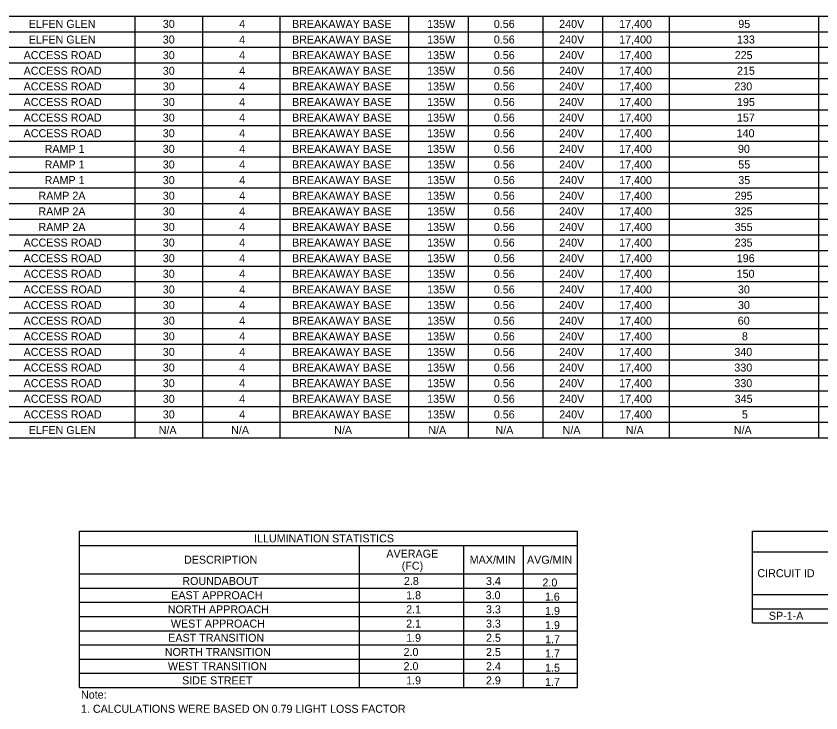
# Model space of a CAD drawing. Extents: x 0.17 to 2.79, y 0.05 to 1.72.
# Drawn here: x 0.862 to 1.859, y 0.093 to 0.956 of the extents above; entities that cross this region are included whole.
import ezdxf

# ---------------------------------------------------------------- set-up
doc = ezdxf.new("R2010")
doc.units = 0
doc.layers.add('Default', color=7, linetype='Continuous')
doc.layers.add('No_Plot', color=7, linetype='Continuous')

msp = doc.modelspace()

# ---------------------------------------------------------------- linework, layer by layer
at = {"layer": 'Default'}
for p, q in [((0.32609, 0.95626), (2.52066, 0.95626)), ((1.0098, 0.43358), (1.0098, 0.95626)), ((1.0934, 0.43358), (1.0934, 0.95626)), ((1.18931, 0.43358), (1.18931, 0.95626)), ((1.34858, 0.43358), (1.34858, 0.95626)), ((1.42249, 0.43358), (1.42249, 0.95626)), ((1.51489, 0.43358), (1.51489, 0.95626)), ((1.5888, 0.43358), (1.5888, 0.95626)), ((1.67152, 0.43358), (1.67152, 0.95626)), ((1.8563, 0.43358), (1.8563, 0.95626)), ((0.32609, 0.9369), (2.52066, 0.9369)), ((0.32609, 0.91754), (2.52066, 0.91754)), ((0.32609, 0.89819), (2.52066, 0.89819)), ((0.32609, 0.87883), (2.52066, 0.87883)), ((0.32609, 0.85947), (2.52066, 0.85947)), ((0.32609, 0.84011), (2.52066, 0.84011)), ((0.32609, 0.82075), (2.52066, 0.82075)), ((0.32609, 0.80139), (2.52066, 0.80139)), ((0.32609, 0.78203), (2.52066, 0.78203)), ((0.32609, 0.76268), (2.52066, 0.76268)), ((0.32609, 0.74332), (2.52066, 0.74332)), ((0.32609, 0.72396), (2.52066, 0.72396)), ((0.32609, 0.7046), (2.52066, 0.7046)), ((0.32609, 0.68524), (2.52066, 0.68524)), ((0.32609, 0.66588), (2.52066, 0.66588)), ((0.32609, 0.64652), (2.52066, 0.64652)), ((0.32609, 0.62716), (2.52066, 0.62716)), ((0.32609, 0.60781), (2.52066, 0.60781)), ((0.32609, 0.58845), (2.52066, 0.58845)), ((0.32609, 0.56909), (2.52066, 0.56909)), ((0.32609, 0.54973), (2.52066, 0.54973)), ((0.32609, 0.53037), (2.52066, 0.53037)), ((0.32609, 0.51101), (2.52066, 0.51101)), ((0.32609, 0.49165), (2.52066, 0.49165)), ((0.32609, 0.4723), (2.52066, 0.4723)), ((0.32609, 0.45294), (2.52066, 0.45294)), ((0.32609, 0.43358), (2.52066, 0.43358)), ((0.94083, 0.31777), (1.55767, 0.31777)), ((0.94083, 0.12418), (0.94083, 0.31777)), ((1.55767, 0.12418), (1.55767, 0.31777)), ((1.7742, 0.31777), (2.64886, 0.31777)), ((1.7742, 0.20426), (1.7742, 0.31777)), ((0.94083, 0.30017), (1.55767, 0.30017)), ((1.28753, 0.12418), (1.28753, 0.30017)), ((1.41688, 0.12418), (1.41688, 0.30017)), ((1.49079, 0.12418), (1.49079, 0.30017)), ((1.7742, 0.29225), (2.64886, 0.29225)), ((0.94083, 0.26497), (1.55767, 0.26497)), ((0.94083, 0.24737), (1.55767, 0.24737)), ((1.7742, 0.23946), (2.64886, 0.23946)), ((0.94083, 0.22978), (1.55767, 0.22978)), ((1.7742, 0.22186), (2.64886, 0.22186)), ((0.94083, 0.21218), (1.55767, 0.21218)), ((1.7742, 0.20426), (2.64886, 0.20426)), ((0.94083, 0.19458), (1.55767, 0.19458)), ((0.94083, 0.17698), (1.55767, 0.17698)), ((0.94083, 0.15938), (1.55767, 0.15938)), ((0.94083, 0.14178), (1.55767, 0.14178)), ((0.94083, 0.12418), (1.55767, 0.12418))]:
    msp.add_line(p, q, dxfattribs=at)
at = {"layer": 'No_Plot'}
for p, q in [((0.94083, 0.31777), (0.94083, 0.31777)), ((1.7742, 0.31777), (1.7742, 0.31777))]:
    msp.add_line(p, q, dxfattribs=at)

# ---------------------------------------------------------------- texts
at = {"layer": 'Default'}
for s, height, p in [('ELFEN GLEN', 0.009927, (0.87792, 0.94162)), ('30', 0.009927, (1.0439, 0.94162)), ('4', 0.00993, (1.13854, 0.94162)), ('BREAKAWAY BASE', 0.0099275, (1.20399, 0.94162)), ('135W', 0.009927, (1.37131, 0.94162)), ('0.56', 0.009927, (1.45388, 0.94162)), ('240V', 0.009927, (1.53484, 0.94162)), ('17,400', 0.009927, (1.60909, 0.94162)), ('95', 0.009927, (1.75664, 0.94162)), ('ELFEN GLEN', 0.009927, (0.87792, 0.92226)), ('30', 0.009927, (1.0439, 0.92226)), ('4', 0.00993, (1.13854, 0.92226)), ('BREAKAWAY BASE', 0.0099275, (1.20399, 0.92226)), ('135W', 0.009927, (1.37131, 0.92226)), ('0.56', 0.009927, (1.45388, 0.92226)), ('240V', 0.009927, (1.53484, 0.92226)), ('17,400', 0.009927, (1.60909, 0.92226)), ('133', 0.009927, (1.755, 0.92226)), ('ACCESS ROAD', 0.0099275, (0.87159, 0.9029)), ('30', 0.009927, (1.0439, 0.9029)), ('4', 0.00993, (1.13854, 0.9029)), ('BREAKAWAY BASE', 0.0099275, (1.20399, 0.9029)), ('135W', 0.009927, (1.37131, 0.9029)), ('0.56', 0.009927, (1.45388, 0.9029)), ('240V', 0.009927, (1.53484, 0.9029)), ('17,400', 0.009927, (1.60909, 0.9029)), ('225', 0.009927, (1.75219, 0.9029)), ('ACCESS ROAD', 0.0099275, (0.87159, 0.88354)), ('30', 0.009927, (1.0439, 0.88354)), ('4', 0.00993, (1.13854, 0.88354)), ('BREAKAWAY BASE', 0.0099275, (1.20399, 0.88354)), ('135W', 0.009927, (1.37131, 0.88354)), ('0.56', 0.009927, (1.45388, 0.88354)), ('240V', 0.009927, (1.53484, 0.88354)), ('17,400', 0.009927, (1.60909, 0.88354)), ('215', 0.009927, (1.755, 0.88354)), ('ACCESS ROAD', 0.0099275, (0.87159, 0.86418)), ('30', 0.009927, (1.0439, 0.86418)), ('4', 0.00993, (1.13854, 0.86418)), ('BREAKAWAY BASE', 0.0099275, (1.20399, 0.86418)), ('135W', 0.009927, (1.37131, 0.86418)), ('0.56', 0.009927, (1.45388, 0.86418)), ('240V', 0.009927, (1.53484, 0.86418)), ('17,400', 0.009927, (1.60909, 0.86418)), ('230', 0.009927, (1.75176, 0.86418)), ('ACCESS ROAD', 0.0099275, (0.87159, 0.84483)), ('30', 0.009927, (1.0439, 0.84483)), ('4', 0.00993, (1.13854, 0.84483)), ('BREAKAWAY BASE', 0.0099275, (1.20399, 0.84483)), ('135W', 0.009927, (1.37131, 0.84483)), ('0.56', 0.009927, (1.45388, 0.84483)), ('240V', 0.009927, (1.53484, 0.84483)), ('17,400', 0.009927, (1.60909, 0.84483)), ('195', 0.009927, (1.755, 0.84483)), ('ACCESS ROAD', 0.0099275, (0.87159, 0.82547)), ('30', 0.009927, (1.0439, 0.82547)), ('4', 0.00993, (1.13854, 0.82547)), ('BREAKAWAY BASE', 0.0099275, (1.20399, 0.82547)), ('135W', 0.009927, (1.37131, 0.82547)), ('0.56', 0.009927, (1.45388, 0.82547)), ('240V', 0.009927, (1.53484, 0.82547)), ('17,400', 0.009927, (1.60909, 0.82547)), ('157', 0.009927, (1.755, 0.82547)), ('ACCESS ROAD', 0.0099275, (0.87159, 0.80611)), ('30', 0.009927, (1.0439, 0.80611)), ('4', 0.00993, (1.13854, 0.80611)), ('BREAKAWAY BASE', 0.0099275, (1.20399, 0.80611)), ('135W', 0.009927, (1.37131, 0.80611)), ('0.56', 0.009927, (1.45388, 0.80611)), ('240V', 0.009927, (1.53484, 0.80611)), ('17,400', 0.009927, (1.60909, 0.80611)), ('140', 0.009927, (1.75457, 0.80611)), ('RAMP 1', 0.009927, (0.89758, 0.78675)), ('30', 0.009927, (1.0439, 0.78675)), ('4', 0.00993, (1.13854, 0.78675)), ('BREAKAWAY BASE', 0.0099275, (1.20399, 0.78675)), ('135W', 0.009927, (1.37131, 0.78675)), ('0.56', 0.009927, (1.45388, 0.78675)), ('240V', 0.009927, (1.53484, 0.78675)), ('17,400', 0.009927, (1.60909, 0.78675)), ('90', 0.009927, (1.75621, 0.78675)), ('30', 0.009927, (1.0439, 0.76739)), ('BREAKAWAY BASE', 0.0099275, (1.20399, 0.76739)), ('135W', 0.009927, (1.37131, 0.76739)), ('0.56', 0.009927, (1.45388, 0.76739)), ('240V', 0.009927, (1.53484, 0.76739)), ('17,400', 0.009927, (1.60909, 0.76739)), ('RAMP 1', 0.009927, (0.89758, 0.76739)), ('4', 0.00993, (1.13854, 0.76739)), ('55', 0.009927, (1.75664, 0.76739)), ('RAMP 1', 0.009927, (0.89758, 0.74803)), ('30', 0.009927, (1.0439, 0.74803)), ('4', 0.00993, (1.13854, 0.74803)), ('BREAKAWAY BASE', 0.0099275, (1.20399, 0.74803)), ('135W', 0.009927, (1.37131, 0.74803)), ('0.56', 0.009927, (1.45388, 0.74803)), ('240V', 0.009927, (1.53484, 0.74803)), ('17,400', 0.009927, (1.60909, 0.74803)), ('35', 0.009927, (1.75664, 0.74803)), ('RAMP 2A', 0.009927, (0.88988, 0.72867)), ('30', 0.009927, (1.0439, 0.72867)), ('4', 0.00993, (1.13854, 0.72867)), ('BREAKAWAY BASE', 0.0099275, (1.20399, 0.72867)), ('135W', 0.009927, (1.37131, 0.72867)), ('0.56', 0.009927, (1.45388, 0.72867)), ('240V', 0.009927, (1.53484, 0.72867)), ('17,400', 0.009927, (1.60909, 0.72867)), ('295', 0.009927, (1.75219, 0.72867)), ('RAMP 2A', 0.009927, (0.88988, 0.70931)), ('30', 0.009927, (1.0439, 0.70931)), ('4', 0.00993, (1.13854, 0.70931)), ('BREAKAWAY BASE', 0.0099275, (1.20399, 0.70931)), ('135W', 0.009927, (1.37131, 0.70931)), ('0.56', 0.009927, (1.45388, 0.70931)), ('240V', 0.009927, (1.53484, 0.70931)), ('17,400', 0.009927, (1.60909, 0.70931)), ('325', 0.009927, (1.75219, 0.70931)), ('RAMP 2A', 0.009927, (0.88988, 0.68996)), ('30', 0.009927, (1.0439, 0.68996)), ('4', 0.00993, (1.13854, 0.68996)), ('BREAKAWAY BASE', 0.0099275, (1.20399, 0.68996)), ('135W', 0.009927, (1.37131, 0.68996)), ('0.56', 0.009927, (1.45388, 0.68996)), ('240V', 0.009927, (1.53484, 0.68996)), ('17,400', 0.009927, (1.60909, 0.68996)), ('355', 0.009927, (1.75219, 0.68996)), ('ACCESS ROAD', 0.0099275, (0.87159, 0.6706)), ('30', 0.009927, (1.0439, 0.6706)), ('4', 0.00993, (1.13854, 0.6706)), ('BREAKAWAY BASE', 0.0099275, (1.20399, 0.6706)), ('135W', 0.009927, (1.37131, 0.6706)), ('0.56', 0.009927, (1.45388, 0.6706)), ('240V', 0.009927, (1.53484, 0.6706)), ('17,400', 0.009927, (1.60909, 0.6706)), ('235', 0.009927, (1.75219, 0.6706)), ('ACCESS ROAD', 0.0099275, (0.87159, 0.65124)), ('30', 0.009927, (1.0439, 0.65124)), ('4', 0.00993, (1.13854, 0.65124)), ('BREAKAWAY BASE', 0.0099275, (1.20399, 0.65124)), ('135W', 0.009927, (1.37131, 0.65124)), ('0.56', 0.009927, (1.45388, 0.65124)), ('240V', 0.009927, (1.53484, 0.65124)), ('17,400', 0.009927, (1.60909, 0.65124)), ('196', 0.009927, (1.75473, 0.65124)), ('ACCESS ROAD', 0.0099275, (0.87159, 0.63188)), ('30', 0.009927, (1.0439, 0.63188)), ('4', 0.00993, (1.13854, 0.63188)), ('BREAKAWAY BASE', 0.0099275, (1.20399, 0.63188)), ('135W', 0.009927, (1.37131, 0.63188)), ('0.56', 0.009927, (1.45388, 0.63188)), ('240V', 0.009927, (1.53484, 0.63188)), ('17,400', 0.009927, (1.60909, 0.63188)), ('150', 0.009927, (1.75457, 0.63188)), ('ACCESS ROAD', 0.0099275, (0.87159, 0.61252)), ('30', 0.009927, (1.0439, 0.61252)), ('4', 0.00993, (1.13854, 0.61252)), ('BREAKAWAY BASE', 0.0099275, (1.20399, 0.61252)), ('135W', 0.009927, (1.37131, 0.61252)), ('0.56', 0.009927, (1.45388, 0.61252)), ('240V', 0.009927, (1.53484, 0.61252)), ('17,400', 0.009927, (1.60909, 0.61252)), ('30', 0.009927, (1.75621, 0.61252)), ('ACCESS ROAD', 0.0099275, (0.87159, 0.59316)), ('30', 0.009927, (1.0439, 0.59316)), ('4', 0.00993, (1.13854, 0.59316)), ('BREAKAWAY BASE', 0.0099275, (1.20399, 0.59316)), ('135W', 0.009927, (1.37131, 0.59316)), ('0.56', 0.009927, (1.45388, 0.59316)), ('240V', 0.009927, (1.53484, 0.59316)), ('17,400', 0.009927, (1.60909, 0.59316)), ('30', 0.009927, (1.75621, 0.59316)), ('ACCESS ROAD', 0.0099275, (0.87159, 0.5738)), ('30', 0.009927, (1.0439, 0.5738)), ('4', 0.00993, (1.13854, 0.5738)), ('BREAKAWAY BASE', 0.0099275, (1.20399, 0.5738)), ('135W', 0.009927, (1.37131, 0.5738)), ('0.56', 0.009927, (1.45388, 0.5738)), ('240V', 0.009927, (1.53484, 0.5738)), ('17,400', 0.009927, (1.60909, 0.5738)), ('60', 0.009927, (1.75598, 0.5738)), ('ACCESS ROAD', 0.0099275, (0.87159, 0.55445)), ('30', 0.009927, (1.0439, 0.55445)), ('4', 0.00993, (1.13854, 0.55445)), ('BREAKAWAY BASE', 0.0099275, (1.20399, 0.55445)), ('135W', 0.009927, (1.37131, 0.55445)), ('0.56', 0.009927, (1.45388, 0.55445)), ('240V', 0.009927, (1.53484, 0.55445)), ('17,400', 0.009927, (1.60909, 0.55445)), ('8', 0.00993, (1.7611, 0.55445)), ('ACCESS ROAD', 0.0099275, (0.87159, 0.53509)), ('30', 0.009927, (1.0439, 0.53509)), ('4', 0.00993, (1.13854, 0.53509)), ('BREAKAWAY BASE', 0.0099275, (1.20399, 0.53509)), ('135W', 0.009927, (1.37131, 0.53509)), ('0.56', 0.009927, (1.45388, 0.53509)), ('240V', 0.009927, (1.53484, 0.53509)), ('17,400', 0.009927, (1.60909, 0.53509)), ('340', 0.009927, (1.75176, 0.53509)), ('ACCESS ROAD', 0.0099275, (0.87159, 0.51573)), ('30', 0.009927, (1.0439, 0.51573)), ('4', 0.00993, (1.13854, 0.51573)), ('BREAKAWAY BASE', 0.0099275, (1.20399, 0.51573)), ('135W', 0.009927, (1.37131, 0.51573)), ('0.56', 0.009927, (1.45388, 0.51573)), ('240V', 0.009927, (1.53484, 0.51573)), ('17,400', 0.009927, (1.60909, 0.51573)), ('330', 0.009927, (1.75176, 0.51573)), ('ACCESS ROAD', 0.0099275, (0.87159, 0.49637)), ('30', 0.009927, (1.0439, 0.49637)), ('4', 0.00993, (1.13854, 0.49637)), ('BREAKAWAY BASE', 0.0099275, (1.20399, 0.49637)), ('135W', 0.009927, (1.37131, 0.49637)), ('0.56', 0.009927, (1.45388, 0.49637)), ('240V', 0.009927, (1.53484, 0.49637)), ('17,400', 0.009927, (1.60909, 0.49637)), ('330', 0.009927, (1.75176, 0.49637)), ('ACCESS ROAD', 0.0099275, (0.87159, 0.47701)), ('30', 0.009927, (1.0439, 0.47701)), ('4', 0.00993, (1.13854, 0.47701)), ('BREAKAWAY BASE', 0.0099275, (1.20399, 0.47701)), ('135W', 0.009927, (1.37131, 0.47701)), ('0.56', 0.009927, (1.45388, 0.47701)), ('240V', 0.009927, (1.53484, 0.47701)), ('17,400', 0.009927, (1.60909, 0.47701)), ('345', 0.009927, (1.75219, 0.47701)), ('ACCESS ROAD', 0.0099275, (0.87159, 0.45765)), ('30', 0.009927, (1.0439, 0.45765)), ('4', 0.00993, (1.13854, 0.45765)), ('BREAKAWAY BASE', 0.0099275, (1.20399, 0.45765)), ('135W', 0.009927, (1.37131, 0.45765)), ('0.56', 0.009927, (1.45388, 0.45765)), ('240V', 0.009927, (1.53484, 0.45765)), ('17,400', 0.009927, (1.60909, 0.45765)), ('5', 0.00993, (1.7611, 0.45765)), ('N/A', 0.009927, (1.03882, 0.43829)), ('N/A', 0.009927, (1.12857, 0.43829)), ('N/A', 0.009927, (1.25616, 0.43829)), ('N/A', 0.009927, (1.37276, 0.43829)), ('N/A', 0.009927, (1.45591, 0.43829)), ('N/A', 0.009927, (1.53906, 0.43829)), ('N/A', 0.009927, (1.61738, 0.43829)), ('N/A', 0.009927, (1.75113, 0.43829)), ('ELFEN GLEN', 0.009927, (0.87792, 0.43829)), ('ILLUMINATION STATISTICS', 0.0099275, (1.15693, 0.30401)), ('AVERAGE', 0.009927, (1.32078, 0.28505)), ('DESCRIPTION', 0.0099275, (1.07021, 0.27761)), ('(FC)', 0.009927, (1.33985, 0.27016)), ('MAX/MIN', 0.009927, (1.42401, 0.27761)), ('AVG/MIN', 0.009927, (1.49496, 0.27761)), ('CIRCUIT ID', 0.009927, (1.78034, 0.26089)), ('ROUNDABOUT', 0.009927, (1.0681, 0.25121)), ('2.8', 0.009927, (1.34251, 0.25121)), ('3.4', 0.009927, (1.44414, 0.25121)), ('2.0', 0.009927, (1.51411, 0.24936)), ('EAST APPROACH', 0.0099275, (1.05438, 0.23361)), ('1.8', 0.009927, (1.34532, 0.23361)), ('3.0', 0.009927, (1.44371, 0.23361)), ('1.6', 0.009927, (1.51708, 0.23176)), ('NORTH APPROACH', 0.0099275, (1.05008, 0.21601)), ('2.1', 0.009927, (1.34532, 0.21601)), ('3.3', 0.009927, (1.44414, 0.21601)), ('1.9', 0.009927, (1.51731, 0.21416)), ('SP-1-A', 0.009927, (1.79448, 0.20809)), ('WEST APPROACH', 0.0099275, (1.05391, 0.19841)), ('2.1', 0.009927, (1.34532, 0.19841)), ('3.3', 0.009927, (1.44414, 0.19841)), ('1.9', 0.009927, (1.51731, 0.19656)), ('EAST TRANSITION', 0.0099275, (1.05067, 0.18082)), ('1.9', 0.009927, (1.34528, 0.18082)), ('2.5', 0.009927, (1.44414, 0.18082)), ('1.7', 0.009927, (1.51735, 0.17896)), ('NORTH TRANSITION', 0.0099275, (1.04637, 0.16322)), ('2.0', 0.009927, (1.34208, 0.16322)), ('2.5', 0.009927, (1.44414, 0.16322)), ('1.7', 0.009927, (1.51735, 0.16137)), ('WEST TRANSITION', 0.0099275, (1.0502, 0.14562)), ('2.0', 0.009927, (1.34208, 0.14562)), ('2.4', 0.009927, (1.44414, 0.14562)), ('1.5', 0.009927, (1.51735, 0.14377)), ('SIDE STREET', 0.0099275, (1.06786, 0.12802)), ('1.9', 0.009927, (1.34528, 0.12802)), ('2.9', 0.009927, (1.4441, 0.12802)), ('1.7', 0.009927, (1.51735, 0.12617)), ('Note:', 0.009927, (0.94259, 0.11042)), ('1. CALCULATIONS WERE BASED ON 0.79 LIGHT LOSS FACTOR', 0.0099275, (0.94259, 0.09282))]:
    msp.add_text(s, height=height, dxfattribs=at).set_placement(p)

doc.saveas('drawing.dxf')
